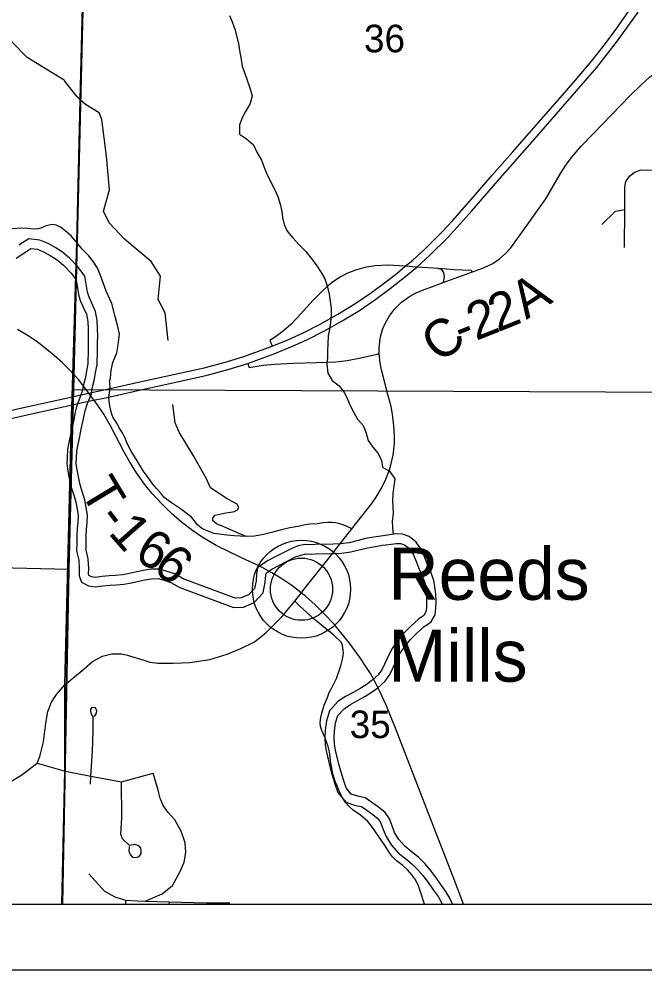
# Model space of a CAD drawing. Extents: x -19 to 40.8, y -1.8 to 26.1.
# Drawn here: x 4.257 to 5.206, y 14 to 15.443 of the extents above; entities that cross this region are included whole.
import ezdxf

# ---------------------------------------------------------------- set-up
doc = ezdxf.new("R2010")
doc.units = 0
for name, color, linetype in [('Default', 7, 'Continuous'), ('GM_X_Corporation', 7, 'Continuous'), ('GM_X_Corporation_Text', 7, 'Continuous'), ('GM_X_County_Road', 7, 'Continuous'), ('GM_X_County_Road_Text', 7, 'Continuous'), ('GM_X_Interchange_Ramps', 7, 'Continuous'), ('GM_X_Major_River', 7, 'Continuous'), ('GM_X_Section', 7, 'Continuous'), ('GM_X_Section_Text', 7, 'Continuous'), ('GM_X_State_Route', 7, 'Continuous'), ('GM_X_Township_Road', 7, 'Continuous'), ('GM_X_Township_Road_Text', 7, 'Continuous'), ('GM_X_Unincorporated', 7, 'Continuous'), ('RW_P_Text', 7, 'Continuous'), ('SH_Data', 7, 'Continuous')]:
    doc.layers.add(name, color=color, linetype=linetype)

msp = doc.modelspace()

# ---------------------------------------------------------------- linework, layer by layer
at = {"layer": 'Default'}
for points in [[(4.3224, 14.1), (5.246, 14.1), (5.2615, 14.8764), (4.3391, 14.8802), (4.3324, 14.6079)], [(3.3277, 14.1), (4.3224, 14.1), (4.3324, 14.6079), (3.3355, 14.6314)]]:
    msp.add_lwpolyline(points, close=True, dxfattribs=at)
at = {"layer": 'GM_X_Corporation'}
msp.add_line((4.6752, 14.5597), (4.6812, 14.5675), dxfattribs=at)
for points in [[(4.9445, 15.0593), (4.9614, 15.0656), (4.9753, 15.0722), (4.9857, 15.0794), (4.9948, 15.0872), (5.0025, 15.096), (5.0244, 15.126), (5.0559, 15.1704), (5.078, 15.2085), (5.0861, 15.2212), (5.0946, 15.233), (5.1095, 15.2502), (5.1273, 15.2688), (5.1552, 15.2975), (5.1839, 15.327), (5.1997, 15.3427), (5.2131, 15.3547), (5.2251, 15.3635), (5.2372, 15.3707), (5.2511, 15.3768), (5.2631, 15.3815)], [(4.8031, 14.9354), (4.8029, 14.9441), (4.8037, 14.9531), (4.805, 14.9606), (4.8082, 14.972), (4.8126, 14.9821), (4.8187, 14.9929), (4.8262, 15.0027), (4.837, 15.0134), (4.8489, 15.0222), (4.8589, 15.0276), (4.871, 15.0326), (4.8829, 15.0369), (4.9001, 15.0432), (4.9445, 15.0593)], [(4.7616, 14.6694), (4.7844, 14.6983), (4.7916, 14.708), (4.7982, 14.7175), (4.8066, 14.7314), (4.8131, 14.7449), (4.8184, 14.7592), (4.8223, 14.7725), (4.8242, 14.7812), (4.8254, 14.7896), (4.826, 14.8001), (4.826, 14.8112), (4.8252, 14.8259), (4.8231, 14.8436), (4.8209, 14.8551), (4.8161, 14.8735), (4.8093, 14.8993), (4.8064, 14.9105), (4.8043, 14.9216), (4.8031, 14.9354)], [(4.6812, 14.5675), (4.6907, 14.58), (4.7229, 14.6206), (4.7616, 14.6694)], [(4.4243, 14.4769), (4.4459, 14.4699), (4.4552, 14.467), (4.4672, 14.4658), (4.4903, 14.4655), (4.5156, 14.4667), (4.5461, 14.4711), (4.5722, 14.479), (4.593, 14.4879), (4.6137, 14.4979), (4.6312, 14.5118), (4.6551, 14.5357), (4.6752, 14.5597)], [(4.2392, 14.2829), (4.2596, 14.2953), (4.284, 14.3139), (4.2882, 14.3238), (4.2936, 14.3464), (4.2971, 14.3747), (4.3002, 14.3924), (4.3058, 14.4065), (4.3133, 14.4182), (4.3263, 14.4329), (4.3351, 14.4404), (4.3552, 14.4569), (4.368, 14.4679), (4.383, 14.4764), (4.3976, 14.4795), (4.412, 14.4797), (4.4214, 14.4779), (4.4243, 14.4769)]]:
    msp.add_lwpolyline(points, dxfattribs=at)
at = {"layer": 'GM_X_County_Road'}
for points in [[(4.9445, 15.0593), (4.9426, 15.0616), (4.9168, 15.0623), (4.8936, 15.0645), (4.8601, 15.0667), (4.8426, 15.0679), (4.8167, 15.0696), (4.797, 15.0687), (4.7814, 15.0661), (4.7671, 15.062), (4.754, 15.0567), (4.7436, 15.0513), (4.7334, 15.0446), (4.724, 15.0373), (4.7147, 15.0287), (4.703, 15.0164), (4.6838, 14.9953), (4.6695, 14.9801), (4.6578, 14.9698), (4.6457, 14.9608), (4.637, 14.9552), (4.6404, 14.9465)], [(4.9001, 15.0432), (4.9011, 15.0465), (4.9021, 15.0519), (4.9017, 15.0556), (4.9005, 15.0591), (4.899, 15.0614), (4.8968, 15.0631), (4.8936, 15.0638), (4.8936, 15.0645)], [(4.6035, 14.9202), (4.6056, 14.9145), (4.627, 14.9178), (4.6441, 14.9195), (4.6728, 14.9209), (4.708, 14.9217), (4.7371, 14.923), (4.7542, 14.9251), (4.7751, 14.9291), (4.8, 14.9344), (4.8031, 14.9354)]]:
    msp.add_lwpolyline(points, dxfattribs=at)
at = {"layer": 'GM_X_Interchange_Ramps'}
msp.add_lwpolyline([(4.9311, 14.1), (4.9151, 14.1413), (4.8815, 14.2282), (4.8396, 14.3355), (4.8278, 14.3668), (4.8137, 14.4016), (4.8046, 14.4215), (4.7957, 14.439), (4.7896, 14.45), (4.7827, 14.4606), (4.7739, 14.4739), (4.7581, 14.4957), (4.7468, 14.5098), (4.7347, 14.5246), (4.7192, 14.5411), (4.7051, 14.5545), (4.6916, 14.5665), (4.6705, 14.5833), (4.6538, 14.5947), (4.64, 14.6028), (4.6277, 14.6099), (4.6163, 14.6152), (4.6008, 14.6226), (4.5776, 14.6336), (4.5559, 14.6439), (4.5342, 14.6568), (4.5198, 14.6669), (4.503, 14.6798), (4.4873, 14.6932), (4.4725, 14.7077), (4.4586, 14.7229), (4.4487, 14.7352), (4.4349, 14.7544), (4.4241, 14.7714), (4.4159, 14.7859), (4.3953, 14.8258), (4.3854, 14.8434), (4.3754, 14.8576), (4.3612, 14.8774), (4.3469, 14.896), (4.3333, 14.9109), (4.3221, 14.922), (4.3099, 14.9327), (4.2963, 14.9437), (4.2841, 14.9531), (4.2703, 14.9621), (4.2543, 14.9719)], dxfattribs=at)
at = {"layer": 'GM_X_Major_River'}
msp.add_line((4.6851, 14.5778), (4.6851, 14.5778), dxfattribs=at)
at = {"layer": 'GM_X_Section'}
for points in [[(4.5758, 15.4485), (4.5798, 15.4387), (4.5838, 15.4277), (4.5896, 15.4058), (4.5913, 15.3952), (4.5935, 15.3815), (4.5952, 15.3717), (4.5988, 15.3619), (4.6028, 15.3505), (4.6069, 15.3388), (4.6102, 15.3263), (4.607, 15.3149), (4.6, 15.303), (4.5949, 15.293), (4.5913, 15.2826), (4.5909, 15.2682), (4.6016, 15.2615), (4.6121, 15.2522), (4.6176, 15.241), (4.6243, 15.2289), (4.6279, 15.2191), (4.6319, 15.2093), (4.6375, 15.1976), (4.6442, 15.1848), (4.649, 15.1739), (4.6527, 15.1622), (4.6552, 15.1512), (4.6565, 15.1417), (4.6586, 15.1315), (4.6634, 15.1213), (4.672, 15.1109), (4.6809, 15.1008), (4.6917, 15.0904), (4.7011, 15.0784), (4.7085, 15.0686), (4.7148, 15.0585), (4.7203, 15.0487), (4.724, 15.0381), (4.7273, 15.0257), (4.7286, 15.0147), (4.73, 15.0044), (4.7302, 14.9942), (4.7293, 14.9827), (4.7276, 14.9721), (4.7255, 14.9625), (4.725, 14.9503), (4.7245, 14.9397), (4.7243, 14.9287), (4.7237, 14.9191), (4.7252, 14.9059), (4.7318, 14.8946), (4.7423, 14.8864), (4.7501, 14.8759), (4.7548, 14.8662), (4.7588, 14.8564), (4.7644, 14.8458), (4.7703, 14.8361), (4.7788, 14.826), (4.7832, 14.8146), (4.7861, 14.8037), (4.7932, 14.7935), (4.8014, 14.7838), (4.8065, 14.7733), (4.8079, 14.763), (4.8186, 14.7572), (4.8268, 14.7452), (4.8252, 14.7341), (4.8239, 14.7231), (4.823, 14.7124), (4.8235, 14.7025), (4.8241, 14.6923), (4.8224, 14.6812), (4.8234, 14.671), (4.8244, 14.6611)], [(4.5058, 14.5936), (4.4928, 14.6009), (4.4811, 14.6049), (4.4693, 14.6081), (4.456, 14.608), (4.4451, 14.6061), (4.4351, 14.604), (4.4243, 14.6014), (4.4138, 14.5996), (4.403, 14.5988), (4.3931, 14.5979), (4.382, 14.597), (4.3725, 14.5957), (4.3664, 14.5968), (4.3627, 14.5986), (4.362, 14.6005), (4.3623, 14.6091), (4.3613, 14.6238), (4.3583, 14.6372), (4.3585, 14.6479), (4.3584, 14.659), (4.359, 14.6684), (4.3601, 14.679), (4.3605, 14.6908), (4.3586, 14.7017), (4.3565, 14.7132), (4.3531, 14.7247), (4.3494, 14.7362), (4.3468, 14.749), (4.3448, 14.7592), (4.3434, 14.7687), (4.3437, 14.7772), (4.3443, 14.7878), (4.3463, 14.7977), (4.3488, 14.8096), (4.351, 14.8209), (4.3536, 14.8319), (4.3554, 14.8413), (4.3577, 14.8506), (4.3607, 14.8594), (4.3663, 14.8745), (4.3683, 14.8851), (4.3713, 14.8968), (4.3728, 14.9066), (4.3751, 14.9182), (4.3757, 14.9409), (4.3757, 14.9516), (4.376, 14.9621), (4.3755, 14.9732), (4.3749, 14.9856), (4.3725, 14.9991), (4.3671, 15.0118), (4.3628, 15.0209), (4.3606, 15.0284), (4.3592, 15.0375), (4.3566, 15.0531), (4.3463, 15.0667), (4.3338, 15.0799), (4.3228, 15.0894), (4.3113, 15.0965), (4.3007, 15.1023), (4.2882, 15.1075), (4.2713, 15.1093), (4.2561, 15.0997)], [(4.2525, 15.0804), (4.2638, 15.0877), (4.2747, 15.0947), (4.2846, 15.0936), (4.2945, 15.0895), (4.3041, 15.0843), (4.3144, 15.0779), (4.324, 15.0696), (4.3355, 15.0575), (4.3432, 15.0473), (4.3452, 15.0352), (4.3468, 15.0253), (4.3495, 15.0158), (4.3541, 15.006), (4.3588, 14.995), (4.3608, 14.984), (4.3613, 14.9726), (4.3617, 14.962), (4.3615, 14.9517), (4.3615, 14.9411), (4.361, 14.9198), (4.3588, 14.9091), (4.3573, 14.8996), (4.3544, 14.8882), (4.3526, 14.8783), (4.3474, 14.8642), (4.344, 14.8547), (4.3415, 14.8444), (4.3397, 14.8349), (4.3371, 14.8238), (4.3349, 14.8124), (4.3324, 14.8006), (4.3302, 14.7896), (4.3295, 14.7778), (4.3292, 14.7679), (4.3308, 14.7569), (4.3328, 14.7463), (4.3356, 14.7326), (4.3395, 14.7205), (4.3426, 14.7099), (4.3446, 14.6993), (4.3462, 14.6898), (4.3459, 14.6799), (4.3449, 14.6696), (4.3442, 14.6594), (4.3443, 14.648), (4.344, 14.6358), (4.3472, 14.6218), (4.348, 14.6088), (4.3478, 14.5982), (4.3513, 14.5884), (4.3619, 14.5831), (4.3722, 14.5813), (4.3836, 14.5829), (4.3942, 14.5838), (4.4041, 14.5846), (4.4155, 14.5855), (4.4272, 14.5874), (4.4382, 14.5902), (4.4477, 14.5922), (4.4572, 14.5938), (4.4675, 14.5939), (4.477, 14.5913), (4.4869, 14.5879), (4.5005, 14.5804)], [(4.9142, 14.1), (4.9101, 14.1089), (4.9042, 14.119), (4.8964, 14.1299), (4.889, 14.1408), (4.8804, 14.152), (4.8722, 14.1617), (4.8625, 14.1711), (4.8517, 14.18), (4.842, 14.1878), (4.8327, 14.1982), (4.8264, 14.2087), (4.8224, 14.2185), (4.8184, 14.2291), (4.8121, 14.2389), (4.8021, 14.247), (4.792, 14.2541), (4.7816, 14.2611), (4.7706, 14.2635), (4.7606, 14.2667), (4.7528, 14.2765), (4.7492, 14.287), (4.7456, 14.2984), (4.7423, 14.3101), (4.7398, 14.3207), (4.7369, 14.3336), (4.7351, 14.343), (4.7346, 14.3529), (4.7351, 14.3624), (4.7368, 14.375), (4.7403, 14.3861), (4.7496, 14.3965), (4.7594, 14.4028), (4.7703, 14.4087), (4.7812, 14.415), (4.7909, 14.4209), (4.801, 14.4283), (4.8118, 14.4384), (4.8192, 14.4485), (4.8236, 14.4581), (4.8283, 14.4677), (4.8338, 14.4792), (4.8408, 14.4892), (4.8497, 14.5008), (4.8601, 14.5109), (4.8713, 14.521), (4.8814, 14.528), (4.8877, 14.5388), (4.889, 14.5491), (4.8892, 14.559), (4.8889, 14.5704), (4.8876, 14.5814), (4.8858, 14.5912), (4.8818, 14.6026), (4.8766, 14.6139), (4.8718, 14.6267), (4.867, 14.6376), (4.8592, 14.6492), (4.8484, 14.6578), (4.8381, 14.6614), (4.8278, 14.6616), (4.8157, 14.6598), (4.8054, 14.6584), (4.7948, 14.6567), (4.7823, 14.6546), (4.771, 14.6517), (4.7574, 14.6484), (4.7445, 14.6466), (4.7331, 14.646), (4.7221, 14.6458), (4.7111, 14.6463), (4.7005, 14.6453), (4.6906, 14.6455), (4.68, 14.6434), (4.6702, 14.6398), (4.6582, 14.6335), (4.645, 14.6271), (4.6326, 14.6204), (4.6184, 14.6102), (4.6167, 14.6007), (4.6161, 14.5904), (4.6137, 14.579), (4.6048, 14.5693), (4.5938, 14.5645), (4.5843, 14.5643), (4.5058, 14.5936)], [(4.5005, 14.5804), (4.5819, 14.5501), (4.5969, 14.5504), (4.6132, 14.5575), (4.6268, 14.5722), (4.6302, 14.5886), (4.6308, 14.5991), (4.6313, 14.6021), (4.6401, 14.6083), (4.6515, 14.6145), (4.6645, 14.6208), (4.676, 14.6268), (4.6839, 14.6297), (4.6919, 14.6313), (4.701, 14.6311), (4.7114, 14.6321), (4.7219, 14.6316), (4.7336, 14.6318), (4.7459, 14.6324), (4.7601, 14.6344), (4.7744, 14.6379), (4.7853, 14.6407), (4.7972, 14.6427), (4.8075, 14.6444), (4.8176, 14.6457), (4.8287, 14.6473), (4.8355, 14.6472), (4.8415, 14.6452), (4.8487, 14.6395), (4.8545, 14.6308), (4.8586, 14.6213), (4.8635, 14.6084), (4.8686, 14.5972), (4.8721, 14.5876), (4.8735, 14.5793), (4.8747, 14.5694), (4.8749, 14.559), (4.8748, 14.5501), (4.8739, 14.5434), (4.8707, 14.5379), (4.8625, 14.5321), (4.8504, 14.5213), (4.8391, 14.5103), (4.8293, 14.4976), (4.8215, 14.4863), (4.8155, 14.4739), (4.8108, 14.4642), (4.8069, 14.4557), (4.8012, 14.4479), (4.7919, 14.4393), (4.783, 14.4327), (4.7739, 14.4273), (4.7633, 14.4211), (4.7521, 14.415), (4.7403, 14.4074), (4.7277, 14.3933), (4.7228, 14.3781), (4.721, 14.3638), (4.7203, 14.3529), (4.721, 14.3413), (4.7229, 14.3307), (4.7259, 14.3175), (4.7285, 14.3066), (4.7319, 14.2943), (4.7357, 14.2826), (4.7402, 14.2695), (4.7522, 14.2545), (4.7669, 14.2498), (4.7759, 14.2478), (4.784, 14.2424), (4.7935, 14.2357), (4.8014, 14.2293), (4.8056, 14.2227), (4.8092, 14.2133), (4.8137, 14.2024), (4.8212, 14.1898), (4.8322, 14.1774), (4.8427, 14.169), (4.8531, 14.1604), (4.8618, 14.152), (4.8693, 14.1431), (4.8775, 14.1325), (4.8848, 14.1218), (4.8923, 14.1113), (4.8975, 14.1024), (4.8986, 14.1)]]:
    msp.add_lwpolyline(points, dxfattribs=at)
at = {"layer": 'GM_X_State_Route'}
for p, q in [((5.1753, 15.0964), (5.1755, 15.154)), ((4.6752, 14.5597), (4.6812, 14.5675)), ((4.418, 14.1058), (4.4179, 14.1)), ((4.4842, 14.1034), (4.4841, 14.1))]:
    msp.add_line(p, q, dxfattribs=at)
msp.add_lwpolyline([(2.1, 15.8991), (2.1, 14.1), (4.3215, 14.1), (4.3262, 14.3024), (4.3261, 14.4335), (4.3369, 14.8581), (4.3371, 14.8653), (4.3373, 14.8703), (4.3441, 15.1043), (4.3494, 15.3211), (4.3628, 15.868), (3.9893, 15.872), (3.7032, 15.8784), (3.0926, 15.8861), (2.1833, 15.8974)], close=True, dxfattribs=at)
for points in [[(4.3257, 15.3498), (4.3251, 15.3505), (4.2689, 15.3849), (4.2466, 15.4076), (4.2199, 15.4459), (4.2025, 15.4933), (4.1605, 15.58), (4.1444, 15.6081), (4.1337, 15.6283), (4.1173, 15.6538), (4.0927, 15.6836), (4.0704, 15.7184), (4.0341, 15.8035), (4.0106, 15.82), (3.993, 15.8334), (3.9881, 15.843), (3.9886, 15.8546), (3.9895, 15.8715), (3.9882, 15.8783)], [(4.3628, 15.868), (4.3494, 15.3211), (4.3441, 15.1043), (4.3373, 14.8703), (4.3371, 14.8653), (4.3369, 14.8581), (4.3261, 14.4335), (4.3262, 14.3024), (4.3215, 14.1), (8.9, 14.1)], [(5.1409, 15.1311), (5.1615, 15.1514), (5.1755, 15.154), (5.1755, 15.1878), (5.1773, 15.1964), (5.1828, 15.2046), (5.1896, 15.2104), (5.2001, 15.2144), (5.2332, 15.2137), (5.2469, 15.2137), (5.2523, 15.2164), (5.2568, 15.2203), (5.2596, 15.2249), (5.2611, 15.2289), (5.2611, 15.2651), (5.2631, 15.3815)], [(4.4828, 14.955), (4.4784, 14.9974), (4.4678, 15.0174), (4.4714, 15.0527), (4.4571, 15.0752), (4.4164, 15.109), (4.3933, 15.1337), (4.3847, 15.1517), (4.394, 15.1841), (4.3894, 15.2348), (4.3821, 15.2904), (4.3781, 15.301), (4.3575, 15.3132), (4.3496, 15.3206), (4.3448, 15.3251), (4.3263, 15.349), (4.3257, 15.3498)], [(4.343, 15.1054), (4.3357, 15.1139), (4.3291, 15.1194), (4.3195, 15.127), (4.316, 15.129), (4.3128, 15.1303), (4.309, 15.1312), (4.3046, 15.1308), (4.2964, 15.1287), (4.2914, 15.1264), (4.2863, 15.1246), (4.2796, 15.1242), (4.2697, 15.1251), (4.2596, 15.1257), (4.2534, 15.1253), (4.2468, 15.1249), (4.2355, 15.1239), (4.2225, 15.1277)], [(4.3941, 14.8923), (4.3952, 14.898), (4.3965, 14.91), (4.3987, 14.9221), (4.4051, 14.9366), (4.4071, 14.9487), (4.409, 14.9648), (4.4064, 14.9765), (4.4027, 14.9916), (4.3974, 15.0114), (4.3886, 15.0301), (4.3798, 15.0556), (4.3759, 15.0648), (4.3695, 15.0747), (4.3625, 15.0839), (4.353, 15.0934), (4.3443, 15.1038), (4.343, 15.1054)], [(4.6014, 14.6577), (4.5832, 14.6588), (4.5716, 14.6599), (4.5519, 14.6622), (4.5387, 14.668), (4.5333, 14.6704), (4.528, 14.675), (4.5181, 14.687), (4.5016, 14.7), (4.4878, 14.7091), (4.4762, 14.7176), (4.4715, 14.7234), (4.4656, 14.73), (4.4596, 14.7373), (4.455, 14.7436), (4.451, 14.7493), (4.4449, 14.7577), (4.4356, 14.7727), (4.4267, 14.7872), (4.4214, 14.7979), (4.419, 14.8032), (4.4172, 14.8081), (4.4134, 14.8151), (4.4086, 14.8225), (4.4062, 14.8281), (4.4024, 14.8338), (4.3996, 14.8379), (4.3976, 14.8436), (4.3959, 14.8492), (4.3948, 14.8542), (4.3937, 14.859), (4.3932, 14.8637), (4.3927, 14.8695), (4.3947, 14.8826), (4.3942, 14.8914), (4.3941, 14.8923)], [(4.6014, 14.6577), (4.5917, 14.6619), (4.5675, 14.6724), (4.556, 14.6772), (4.5504, 14.6814), (4.5504, 14.6863), (4.5541, 14.6901), (4.5678, 14.693), (4.5833, 14.6958), (4.5878, 14.6981), (4.5902, 14.7019), (4.5874, 14.7069), (4.5725, 14.7149), (4.5473, 14.7316), (4.541, 14.7453), (4.5215, 14.78), (4.4993, 14.8161), (4.4933, 14.8305), (4.4901, 14.8583)], [(4.7616, 14.6694), (4.7542, 14.673), (4.7481, 14.6753), (4.7413, 14.6777), (4.7368, 14.6786), (4.7318, 14.6788), (4.7252, 14.6788), (4.7173, 14.6785), (4.7094, 14.677), (4.6979, 14.6763), (4.6907, 14.6755), (4.6826, 14.6737), (4.6676, 14.6708), (4.6527, 14.6675), (4.6397, 14.664), (4.6276, 14.6607), (4.6137, 14.6585), (4.6014, 14.6577)], [(4.6812, 14.5675), (4.6907, 14.58), (4.7229, 14.6206), (4.7616, 14.6694)], [(4.8715, 14.1), (4.8651, 14.1199), (4.862, 14.1291), (4.8572, 14.1384), (4.8526, 14.1446), (4.8465, 14.1515), (4.8388, 14.1584), (4.829, 14.1657), (4.8231, 14.1716), (4.8186, 14.1779), (4.8118, 14.1885), (4.7917, 14.2178), (4.7858, 14.2253), (4.7746, 14.2347), (4.7634, 14.2424), (4.7568, 14.2487), (4.7516, 14.2542), (4.7468, 14.2621), (4.743, 14.2705), (4.7399, 14.2784), (4.7368, 14.2852), (4.7338, 14.2943), (4.7314, 14.3033), (4.7298, 14.3138), (4.7285, 14.3222), (4.7274, 14.3308), (4.7257, 14.3393), (4.723, 14.3464), (4.7199, 14.3545), (4.7158, 14.3635), (4.7138, 14.3697), (4.7135, 14.3756), (4.7144, 14.3831), (4.7157, 14.3895), (4.7195, 14.4018), (4.7243, 14.4136), (4.7272, 14.4209), (4.7311, 14.4279), (4.7344, 14.4341), (4.7381, 14.4423), (4.7432, 14.4571), (4.7451, 14.4635), (4.7474, 14.4715), (4.7487, 14.4802), (4.7485, 14.4855), (4.7472, 14.4925), (4.7456, 14.4967), (4.734, 14.5079), (4.7186, 14.5209), (4.7122, 14.5257), (4.7025, 14.5337), (4.6927, 14.5429), (4.6826, 14.5521), (4.6752, 14.5597)], [(4.3648, 14.2821), (4.3654, 14.2939), (4.3679, 14.3322), (4.3692, 14.3626), (4.3693, 14.3844), (4.3668, 14.3882), (4.3654, 14.3927), (4.3655, 14.3959), (4.3682, 14.3986), (4.3717, 14.3984), (4.3733, 14.3964), (4.374, 14.3933), (4.3734, 14.3897), (4.3705, 14.3845)], [(4.284, 14.3139), (4.3264, 14.3018), (4.3324, 14.3006)], [(4.3324, 14.3006), (4.3654, 14.2939), (4.412, 14.2854), (4.4601, 14.2988)], [(4.3623, 14.1461), (4.3865, 14.1195), (4.4019, 14.1111), (4.418, 14.1058), (4.4359, 14.1048), (4.4481, 14.1044), (4.4735, 14.1154), (4.4892, 14.128), (4.5013, 14.1494), (4.5069, 14.1637), (4.5095, 14.178), (4.5085, 14.1927), (4.5027, 14.2104), (4.4928, 14.2277), (4.4829, 14.2391), (4.4751, 14.2495), (4.4705, 14.2605), (4.4675, 14.2728), (4.4601, 14.2988)], [(4.4238, 14.1871), (4.4231, 14.1801), (4.4252, 14.1754), (4.4288, 14.1714), (4.4342, 14.1705), (4.4391, 14.1724), (4.442, 14.1766), (4.442, 14.1814), (4.4412, 14.185), (4.4385, 14.1885), (4.4321, 14.1904), (4.4244, 14.189), (4.4135, 14.199), (4.4113, 14.2062), (4.4127, 14.2309), (4.412, 14.2854)], [(4.4481, 14.1044), (4.4842, 14.1034), (4.5405, 14.102), (4.5766, 14.102)]]:
    msp.add_lwpolyline(points, dxfattribs=at)
at = {"layer": 'GM_X_Township_Road'}
for points in [[(4.6404, 14.9465), (4.6646, 14.9564), (4.6865, 14.9664), (4.7134, 14.9802), (4.7402, 14.9952), (4.7662, 15.0111), (4.7911, 15.028), (4.813, 15.0441), (4.83, 15.0573), (4.8426, 15.0679), (4.8538, 15.0774), (4.8725, 15.0943), (4.8986, 15.1202), (4.9141, 15.1368), (4.9393, 15.1655), (4.9745, 15.2059), (5.0054, 15.2412), (5.0304, 15.2699), (5.0552, 15.2983), (5.0808, 15.3276), (5.1008, 15.3505), (5.1256, 15.3798), (5.1447, 15.4038), (5.1635, 15.429), (5.1894, 15.4661)], [(4.6035, 14.9202), (4.6448, 14.9353), (4.6714, 14.9464), (4.6932, 14.9563), (4.7201, 14.9701), (4.7469, 14.9852), (4.7729, 15.001), (4.7979, 15.018), (4.8197, 15.034), (4.8433, 15.0527), (4.8601, 15.0667), (4.8792, 15.0843), (4.907, 15.1116), (4.9265, 15.1327), (4.9436, 15.1522), (4.9829, 15.1974), (5.0384, 15.2608), (5.0886, 15.3184), (5.1329, 15.3697), (5.1646, 15.41), (5.1956, 15.4536)], [(4.2003, 14.8392), (4.2682, 14.8544), (4.3192, 14.8657), (4.3375, 14.8698), (4.3575, 14.8742), (4.3947, 14.8826), (4.4397, 14.8923), (4.4792, 14.901), (4.5376, 14.9139), (4.5711, 14.9228), (4.5991, 14.9314), (4.6404, 14.9465)], [(4.4127, 14.8739), (4.4479, 14.8817), (4.4852, 14.8899), (4.542, 14.9027), (4.5755, 14.9116), (4.6035, 14.9202)], [(4.2047, 14.828), (4.271, 14.8427), (4.3236, 14.8545), (4.3371, 14.8575), (4.3619, 14.863), (4.3927, 14.8695), (4.4127, 14.8739)]]:
    msp.add_lwpolyline(points, dxfattribs=at)
at = {"layer": 'GM_X_Unincorporated'}
for radius in [0.0744, 0.0472]:
    msp.add_circle((4.6851, 14.5778), radius, dxfattribs=at)
at = {"layer": 'RW_P_Text'}
for points in [[(4.3678, 15.9788), (5.2848, 15.9609), (5.2615, 14.8764), (4.3391, 14.8802), (4.3635, 15.8676)], [(3.3595, 15.883), (4.3635, 15.8676), (4.3391, 14.8802), (4.3324, 14.6079), (3.3355, 14.6314)]]:
    msp.add_lwpolyline(points, close=True, dxfattribs=at)
at = {"layer": 'SH_Data'}
for p, q in [((2.1, 14.1), (8.9, 14.1)), ((2, 14), (9, 14))]:
    msp.add_line(p, q, dxfattribs=at)

# ---------------------------------------------------------------- texts
at = {"layer": 'GM_X_Corporation_Text'}
for s, p in [('Reeds', (4.8169, 14.5617)), ('Mills', (4.8169, 14.4375))]:
    msp.add_text(s, height=0.07898, rotation=0, dxfattribs=at).set_placement(p)
at = {"layer": 'GM_X_County_Road_Text'}
for s, rotation, p in [('A', 33.3862, (5.0261, 14.9863)), ('2', 21.8428, (4.9825, 14.9675)), ('2', 21.6043, (4.9497, 14.9545)), ('C', 36.8699, (4.8942, 14.9198)), ('-', 21.8014, (4.9281, 14.9459))]:
    msp.add_text(s, height=0.0568, rotation=rotation, dxfattribs=at).set_placement(p)
at = {"layer": 'GM_X_Section_Text'}
for s, p in [('36', (4.7799, 15.3926)), ('35', (4.7582, 14.3518))]:
    msp.add_text(s, height=0.04186, rotation=0, dxfattribs=at).set_placement(p)
at = {"layer": 'GM_X_Township_Road_Text'}
for s, rotation, p in [('T', 301.1074, (4.3481, 14.7266)), ('-', 307.4318, (4.3738, 14.6846)), ('1', 311.325, (4.3906, 14.663)), ('6', 330.4356, (4.4294, 14.6239)), ('6', 319.7008, (4.4573, 14.6084))]:
    msp.add_text(s, height=0.0568, rotation=rotation, dxfattribs=at).set_placement(p)

doc.saveas('drawing.dxf')
